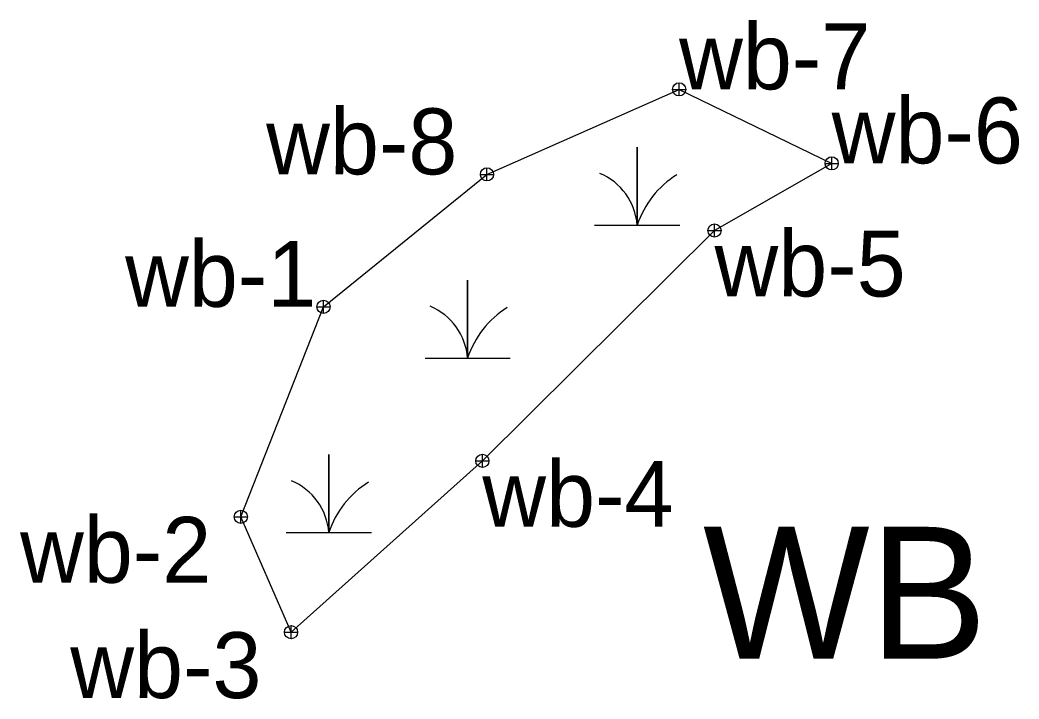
# Model space of a CAD drawing. Extents: x 1623201 to 1624143, y 886383 to 888508.
# Drawn here: x 1623690.3 to 1623766.1, y 888009 to 888060.6 of the extents above; entities that cross this region are included whole.
import ezdxf

# ---------------------------------------------------------------- set-up
doc = ezdxf.new("R2010")
doc.units = 0
for name, color, linetype in [('BR0168_Potential__x0020__Non__x002D__wetland__x0020__WOUS__x0020____x0028__Streams__x0029__', 7, 'Continuous'), ('BR0168_Potential__x0020__Non__x002D__wetland__x0020__WOUS__x0020____x0028__Surface__x0020__Waters__x0029__', 7, 'Continuous'), ('BR0168_Potential_Wetland_WOUS', 7, 'Continuous'), ('Default', 7, 'Continuous'), ('Exist Structure Major Bridge WW', 7, 'Continuous')]:
    doc.layers.add(name, color=color, linetype=linetype)

# ---------------------------------------------------------------- blocks, each defined once
blk = doc.blocks.new('SurveyPointCell')
at = {"layer": 'Default'}
for p, q in [((-0.5, 0), (0.5, 0)), ((0, -0.5), (0, 0.5))]:
    blk.add_line(p, q, dxfattribs=at)
blk.add_circle((0, 0), 0.5, dxfattribs=at)

msp = doc.modelspace()

# ---------------------------------------------------------------- linework, layer by layer
at = {"layer": 'BR0168_Potential_Wetland_WOUS'}
msp.add_lwpolyline([(1623710.868, 888014.107), (1623707.063, 888022.854), (1623713.33, 888038.79), (1623725.718, 888048.84), (1623740.288, 888055.286), (1623751.853, 888049.672), (1623742.971, 888044.575), (1623725.369, 888027.101)], close=True, dxfattribs=at)
at = {"layer": 'Exist Structure Major Bridge WW'}
for points in [[(1623733.883, 888044.984), (1623737.109, 888044.984), (1623737.109, 888050.901), (1623737.109, 888044.984), (1623740.334, 888044.984)], [(1623721.023, 888034.9), (1623724.248, 888034.9), (1623724.248, 888040.818), (1623724.248, 888034.9), (1623727.474, 888034.9)], [(1623710.506, 888021.665), (1623713.731, 888021.665), (1623713.731, 888027.583), (1623713.731, 888021.665), (1623716.957, 888021.665)]]:
    msp.add_lwpolyline(points, dxfattribs=at)
for centre, radius, start, end in [((1623732.509, 888044.651), 4.612, 4.14034, 67.53497), ((1623743.95, 888042.711), 7.208, 122.12745, 161.62219), ((1623719.648, 888034.567), 4.612, 4.14034, 67.53497), ((1623731.089, 888032.627), 7.208, 122.12745, 161.62219), ((1623709.131, 888021.332), 4.612, 4.14034, 67.53497), ((1623720.572, 888019.392), 7.208, 122.12745, 161.62219)]:
    msp.add_arc(centre, radius, start, end, dxfattribs=at)

# ---------------------------------------------------------------- block references
at = {"layer": 'Default'}
for p in [(1623740.288, 888055.286), (1623751.853, 888049.672), (1623725.718, 888048.84), (1623742.971, 888044.575), (1623713.33, 888038.79), (1623725.369, 888027.101), (1623707.063, 888022.854), (1623710.868, 888014.107)]:
    msp.add_blockref('SurveyPointCell', p, dxfattribs=at)

# ---------------------------------------------------------------- texts
at = {"layer": 'BR0168_Potential__x0020__Non__x002D__wetland__x0020__WOUS__x0020____x0028__Streams__x0029__'}
msp.add_text('WB', height=10, dxfattribs=at).set_placement((1623742.101, 888012.101))
at = {"layer": 'BR0168_Potential__x0020__Non__x002D__wetland__x0020__WOUS__x0020____x0028__Surface__x0020__Waters__x0029__'}
for s, p in [('wb-7', (1623740.288, 888055.286)), ('wb-6', (1623751.853, 888049.672)), ('wb-8', (1623708.985, 888048.84)), ('wb-5', (1623742.971, 888039.575)), ('wb-1', (1623698.291, 888038.79)), ('wb-4', (1623725.369, 888022.101)), ('wb-2', (1623690.33, 888017.854)), ('wb-3', (1623694.135, 888009.107))]:
    msp.add_text(s, height=5, dxfattribs=at).set_placement(p)

doc.saveas('drawing.dxf')
